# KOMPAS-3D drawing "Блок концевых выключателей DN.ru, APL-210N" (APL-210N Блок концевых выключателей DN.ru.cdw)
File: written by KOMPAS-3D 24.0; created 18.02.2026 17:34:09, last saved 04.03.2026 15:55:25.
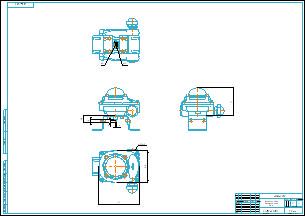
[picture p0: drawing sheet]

Document properties: Автор: R2D2; Форматы листов документа: A1; Полное имя файла: APL-210N Блок концевых выключателей DN.ru.m3d; Масса: 0.22; Наименование: Блок концевых выключателей DN.ru; Количество листов документа: 1; Примечание: D290-00322

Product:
- Part/product: Блок концевых выключателей DN.ru  | designation APL-210N
    Масса: 0.22
    Раздел спецификации: Прочие изделия
    Примечание: D290-00322

Referenced files in E:\Работа\Зайцев\Для компаса\: чертеж DN.ru А3.cdt
Referenced files in E:\Работа\Зайцев\!готово\Аксессуары для пневмоприводов\Блок концевых выключателей DN.ru\APL-210N Блок концевых выключателей DN.ru\: APL-210N Блок концевых выключателей DN.ru.m3d
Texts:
  чертеж DN.ru А3.cdt
  Блок концевых
  выключателей
  APL-210N
  Блок концевых выключателей DN.ru
  APL-210N Блок концевых выключателей DN.ru
Dimensions and other numbers on the sheet: 1:1; 0; 1; 2; 0,22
